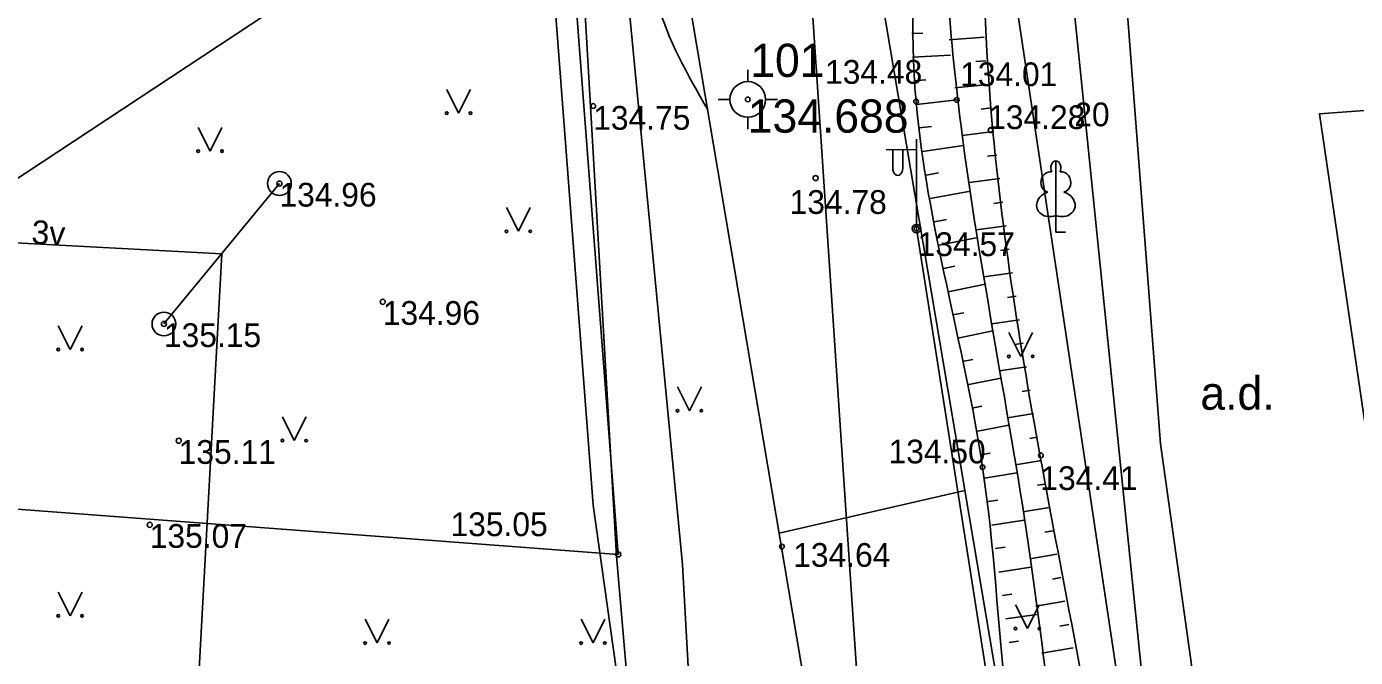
# Model space of a CAD drawing. Extents: x 728710 to 728960, y 272811 to 273475.
# Drawn here: x 728760.53 to 728788.49, y 273391.98 to 273405.27 of the extents above; entities that cross this region are included whole.
import ezdxf

# ---------------------------------------------------------------- set-up
doc = ezdxf.new("R2010")
doc.units = 0
for name, color, linetype in [('Level 10', 7, 'Continuous'), ('Level 12', 7, 'Continuous'), ('Level 15', 7, 'Continuous'), ('Level 18', 7, 'Continuous'), ('Level 20', 7, 'Continuous'), ('Level 21', 7, 'Continuous'), ('Level 23', 7, 'Continuous'), ('Level 25', 7, 'Continuous'), ('Level 26', 7, 'Continuous'), ('Level 28', 7, 'Continuous'), ('Level 30', 7, 'Continuous'), ('Level 32', 7, 'Continuous'), ('Level 34', 7, 'Continuous'), ('Level 35', 7, 'Continuous'), ('Level 4', 7, 'Continuous'), ('Level 42', 7, 'Continuous'), ('Level 48', 7, 'Continuous'), ('Level 53', 7, 'Continuous'), ('Level 57', 7, 'Continuous'), ('Level 63', 7, 'Continuous'), ('Level 8', 7, 'Continuous'), ('RAMI_UZMR_####_####_#', 7, 'Continuous'), ('RELJ_NOGA_####_####_#', 7, 'Continuous'), ('ROBZ_ELEM_####_####_#', 7, 'Continuous'), ('ROBZ_UZMR_####_####_#', 7, 'Continuous'), ('TERT_KOKR_####_####_#', 7, 'Continuous'), ('TERT_KONT_####_####_#', 7, 'Continuous')]:
    doc.layers.add(name, color=color, linetype=linetype)

msp = doc.modelspace()

# ---------------------------------------------------------------- linework, layer by layer
at = {"layer": 'Level 10'}
for p, q in [((728775.704, 273404.108), (728775.704, 273404.358)), ((728775.079, 273403.733), (728775.329, 273403.733)), ((728776.079, 273403.733), (728776.329, 273403.733)), ((728775.704, 273403.108), (728775.704, 273403.358))]:
    msp.add_line(p, q, dxfattribs=at)
for radius in [0.375, 0.05]:
    msp.add_circle((728775.704, 273403.733), radius, dxfattribs=at)
at = {"layer": 'Level 12'}
for p, q in [((728779.155, 273405.124), (728779.386, 273405.129)), ((728780.676, 273405.047), (728779.94, 273404.99)), ((728779.172, 273404.624), (728779.974, 273404.666)), ((728780.717, 273404.548), (728780.501, 273404.529)), ((728779.204, 273404.125), (728779.453, 273404.145)), ((728780.765, 273404.051), (728780.064, 273403.976)), ((728779.253, 273403.628), (728780.101, 273403.724)), ((728780.821, 273403.554), (728780.616, 273403.53)), ((728779.314, 273403.132), (728779.572, 273403.165)), ((728780.881, 273403.057), (728780.214, 273402.975)), ((728779.383, 273402.636), (728780.245, 273402.766)), ((728780.943, 273402.561), (728780.747, 273402.536)), ((728779.46, 273402.142), (728779.718, 273402.185)), ((728781.007, 273402.065), (728780.366, 273401.982)), ((728779.544, 273401.649), (728780.394, 273401.799)), ((728781.072, 273401.57), (728780.884, 273401.544)), ((728779.633, 273401.157), (728779.884, 273401.204)), ((728781.14, 273401.074), (728780.521, 273400.989)), ((728779.726, 273400.666), (728780.547, 273400.825)), ((728781.208, 273400.579), (728781.026, 273400.553)), ((728779.822, 273400.176), (728780.063, 273400.224)), ((728781.279, 273400.084), (728780.679, 273399.998)), ((728779.922, 273399.685), (728780.703, 273399.845)), ((728781.351, 273399.589), (728781.173, 273399.563)), ((728780.022, 273399.196), (728780.25, 273399.243)), ((728780.123, 273398.706), (728780.864, 273398.858)), ((728781.423, 273399.094), (728780.84, 273399.008)), ((728781.498, 273398.6), (728781.325, 273398.574)), ((728780.223, 273398.216), (728780.44, 273398.26)), ((728781.573, 273398.106), (728781.004, 273398.018)), ((728780.322, 273397.726), (728781.03, 273397.867)), ((728781.649, 273397.612), (728781.481, 273397.585)), ((728780.419, 273397.235), (728780.627, 273397.276)), ((728780.512, 273396.744), (728781.198, 273396.872)), ((728781.727, 273397.118), (728781.171, 273397.03)), ((728781.805, 273396.624), (728781.64, 273396.597)), ((728780.6, 273396.252), (728780.805, 273396.288)), ((728781.884, 273396.13), (728781.337, 273396.042)), ((728780.683, 273395.759), (728781.366, 273395.872)), ((728781.964, 273395.636), (728781.8, 273395.61)), ((728780.763, 273395.265), (728780.968, 273395.299)), ((728782.045, 273395.143), (728781.495, 273395.053)), ((728780.841, 273394.772), (728781.521, 273394.878)), ((728782.127, 273394.65), (728781.959, 273394.622)), ((728780.917, 273394.277), (728781.12, 273394.308)), ((728782.21, 273394.157), (728781.637, 273394.06)), ((728780.991, 273393.783), (728781.661, 273393.883)), ((728782.293, 273393.664), (728782.116, 273393.634)), ((728781.065, 273393.288), (728781.263, 273393.317)), ((728782.378, 273393.171), (728781.768, 273393.065)), ((728781.137, 273392.794), (728781.791, 273392.888)), ((728782.464, 273392.678), (728782.274, 273392.646)), ((728781.208, 273392.299), (728781.402, 273392.327)), ((728782.549, 273392.186), (728781.896, 273392.073))]:
    msp.add_line(p, q, dxfattribs=at)
msp.add_spline([(728781.578, 273417.978), (728780.943, 273413.169), (728780.822, 273403.542), (728781.949, 273395.724), (728783.589, 273385.96), (728783.878, 273383.473), (728783.979, 273382.874), (728783.979, 273382.553), (728783.717, 273382.35), (728783.447, 273382.528), (728783.355, 273382.891), (728782.193, 273386.189), (728780.645, 273395.989), (728779.246, 273403.69), (728779.989, 273412.965), (728780.695, 273417.894)], degree=3, dxfattribs=at)
at = {"layer": 'Level 15'}
for centre in [(728765.847, 273401.963), (728763.417, 273399.005)]:
    msp.add_circle(centre, 0.25, dxfattribs=at)
at = {"layer": 'Level 18'}
msp.add_lwpolyline([(728779.523, 273368.911), (728776.197, 273418.56)], dxfattribs=at)
at = {"layer": 'Level 20'}
msp.add_line((728763.417, 273399.005), (728765.848, 273401.962), dxfattribs=at)
at = {"layer": 'Level 21'}
for p, q in [((728764.632, 273400.484), (728747.755, 273401.368)), ((728763.288, 273375.684), (728764.632, 273400.484))]:
    msp.add_line(p, q, dxfattribs=at)
at = {"layer": 'Level 23'}
msp.add_lwpolyline([(728775.104, 273411.821), (728750.664, 273395.692)], dxfattribs=at)
at = {"layer": 'Level 25'}
msp.add_lwpolyline([(728786.021, 273373.071), (728785.768, 273373.044), (728785.616, 273373.092), (728785.488, 273373.338), (728782.365, 273382.337), (728780.872, 273390.743), (728779.255, 273401.013)], dxfattribs=at)
at = {"layer": 'Level 26'}
for p, q in [((728779.255, 273401.013), (728779.255, 273402.896)), ((728779.255, 273402.68), (728778.62, 273402.675)), ((728778.755, 273402.676), (728778.755, 273402.284)), ((728778.965, 273402.678), (728778.965, 273402.284))]:
    msp.add_line(p, q, dxfattribs=at)
msp.add_circle((728779.255, 273401.013), 0.09, dxfattribs=at)
msp.add_ellipse((728778.86, 273402.284), major_axis=(0, 0.151), ratio=0.695971, start_param=1.570796, end_param=4.712389, dxfattribs=at)
at = {"layer": 'Level 28'}
msp.add_lwpolyline([(728781.258, 273406.444), (728784.764, 273383.035), (728785.687, 273382.659)], dxfattribs=at)
at = {"layer": 'Level 30'}
msp.add_spline([(728780.467, 273412.725), (728778.825, 273413.003), (728776.905, 273413.509), (728774.681, 273413.282), (728773.747, 273411.312), (728773.47, 273409.648), (728773.521, 273407.852), (728773.798, 273405.783), (728774.861, 273403.52)], degree=3, dxfattribs=at)
at = {"layer": 'Level 32'}
msp.add_line((728776.368, 273394.599), (728780.273, 273395.496), dxfattribs=at)
at = {"layer": 'Level 34'}
msp.add_spline([(728781.172, 273417.937), (728780.8, 273415.225), (728779.913, 273408.639), (728779.913, 273406.196), (728780.192, 273403.172), (728781.656, 273394.054), (728782.888, 273385.843), (728783.581, 273383.144)], degree=3, dxfattribs=at)
at = {"layer": 'Level 35'}
msp.add_lwpolyline([(728757.526, 273395.316), (728772.98, 273394.153)], dxfattribs=at)
at = {"layer": 'Level 4'}
for p, q in [((728781.219, 273389.895), (728777.803, 273410.117)), ((728777.326, 273388.924), (728773.859, 273409.451))]:
    msp.add_line(p, q, dxfattribs=at)
at = {"layer": 'Level 42'}
msp.add_lwpolyline([(728744.127, 273417.336), (728753.529, 273417.32), (728763.941, 273415.674), (728771.995, 273414.301), (728772.789, 273413.658), (728772.866, 273409.228), (728774.333, 273393.944), (728774.498, 273390.902), (728774.316, 273388.778), (728772.706, 273388.348), (728772.062, 273387.726), (728772.188, 273385.974), (728773.233, 273385.001), (728774.349, 273385.73), (728774.847, 273385.541), (728775.23, 273379.296), (728776.795, 273371.75), (728778.361, 273363.303)], dxfattribs=at)
at = {"layer": 'Level 48'}
for centre, radius in [((728772.451, 273403.594), 0.05), ((728775.704, 273403.733), 0.05), ((728779.246, 273403.69), 0.05), ((728780.101, 273403.724), 0.05), ((728780.814, 273403.086), 0.05), ((728765.848, 273401.962), 0.0534), ((728777.133, 273402.077), 0.0534), ((728779.255, 273401.013), 0.05), ((728768.023, 273399.472), 0.0534), ((728763.417, 273399.006), 0.0534), ((728763.728, 273396.546), 0.0534), ((728780.645, 273395.989), 0.05), ((728781.874, 273396.239), 0.05), ((728763.119, 273394.777), 0.0534), ((728776.423, 273394.317), 0.05), ((728772.98, 273394.153), 0.0534)]:
    msp.add_circle(centre, radius, dxfattribs=at)
at = {"layer": 'Level 8'}
msp.add_line((728772.98, 273394.153), (728771.877, 273408.545), dxfattribs=at)
at = {"layer": 'RAMI_UZMR_####_####_#'}
msp.add_lwpolyline([(728810.773, 273260.978), (728802.611, 273315.901), (728795.796, 273348.362), (728794.274, 273357.438), (728805.771, 273362.009), (728805.234, 273373.998), (728803.936, 273379.727), (728791.234, 273379.578), (728787.734, 273403.429), (728803.558, 273404.599), (728803.908, 273418.239), (728787.419, 273421.679), (728754.475, 273424.404), (728743.982, 273420.563), (728745.23, 273392.888), (728745.879, 273378.489), (728747.149, 273361.103), (728773.116, 273356.557), (728775.22, 273317.659), (728767.872, 273315.668), (728768.286, 273308.258), (728775.846, 273306.093), (728776.746, 273299.712), (728774.767, 273288.109)], dxfattribs=at)
at = {"layer": 'ROBZ_ELEM_####_####_#'}
for points in [[(728775.108, 273376.265), (728772.453, 273395.191), (728770.82, 273416.523)], [(728787.679, 273373.026), (728784.39, 273396.483), (728782.92, 273415.669)]]:
    msp.add_lwpolyline(points, dxfattribs=at)
at = {"layer": 'ROBZ_UZMR_####_####_#'}
for p, q in [((728772.942, 273394.12), (728771.692, 273415.636)), ((728784.885, 273382.939), (728782.32, 273408.103)), ((728774.702, 273373.447), (728772.942, 273394.12))]:
    msp.add_line(p, q, dxfattribs=at)
at = {"layer": 'TERT_KONT_####_####_#'}
for p, q in [((728769.368, 273403.944), (728769.618, 273403.444)), ((728769.618, 273403.444), (728769.868, 273403.944)), ((728764.138, 273403.143), (728764.388, 273402.643)), ((728764.388, 273402.643), (728764.638, 273403.143)), ((728770.626, 273401.456), (728770.876, 273400.956)), ((728770.876, 273400.956), (728771.126, 273401.456)), ((728782.189, 273401.287), (728782.189, 273400.94)), ((728782.189, 273400.94), (728782.389, 273400.94)), ((728761.194, 273398.967), (728761.444, 273398.467)), ((728761.444, 273398.467), (728761.694, 273398.967)), ((728781.2, 273398.824), (728781.45, 273398.324)), ((728781.45, 273398.324), (728781.7, 273398.824)), ((728774.227, 273397.68), (728774.477, 273397.18)), ((728774.477, 273397.18), (728774.727, 273397.68)), ((728765.91, 273397.051), (728766.16, 273396.551)), ((728766.16, 273396.551), (728766.41, 273397.051)), ((728761.194, 273393.361), (728761.444, 273392.861)), ((728761.444, 273392.861), (728761.694, 273393.361)), ((728781.339, 273393.091), (728781.589, 273392.591)), ((728781.589, 273392.591), (728781.839, 273393.091)), ((728767.653, 273392.789), (728767.903, 273392.289)), ((728767.903, 273392.289), (728768.153, 273392.789)), ((728772.198, 273392.789), (728772.448, 273392.289)), ((728772.448, 273392.289), (728772.698, 273392.789))]:
    msp.add_line(p, q, dxfattribs=at)
for points in [[(728782.189, 273402.44), (728782.189, 273401.287)], [(728782.278, 273402.208), (728782.277, 273402.209)]]:
    msp.add_lwpolyline(points, dxfattribs=at)
for centre, radius in [((728769.368, 273403.444), 0.028), ((728769.868, 273403.444), 0.0263), ((728764.138, 273402.643), 0.028), ((728764.638, 273402.643), 0.0263), ((728770.626, 273400.955), 0.028), ((728771.126, 273400.955), 0.0263), ((728761.194, 273398.467), 0.028), ((728761.694, 273398.467), 0.0263), ((728781.2, 273398.323), 0.028), ((728781.7, 273398.323), 0.0263), ((728774.227, 273397.18), 0.028), ((728774.727, 273397.18), 0.0263), ((728765.91, 273396.55), 0.028), ((728766.41, 273396.55), 0.0263), ((728761.194, 273392.86), 0.028), ((728761.694, 273392.86), 0.0263), ((728781.339, 273392.591), 0.028), ((728781.839, 273392.591), 0.0263), ((728767.653, 273392.288), 0.028), ((728768.153, 273392.288), 0.0263), ((728772.197, 273392.288), 0.028), ((728772.697, 273392.288), 0.0263)]:
    msp.add_circle(centre, radius, dxfattribs=at)
for centre, major_axis, ratio, start_param, end_param in [((728782.06, 273401.995), (-0.039, -0.212), 0.861323, 3.141593, 6.283185), ((728782.189, 273402.29), (0, -0.15), 0.707107, 3.14537, 5.287485), ((728782.188, 273402.29), (0, -0.15), 0.707107, 0.995701, 3.137816), ((728782.317, 273401.995), (0.039, -0.212), 0.861323, 0, 3.141593), ((728782.099, 273401.533), (0.307, 0.095), 0.814445, 1.570796, 4.752015), ((728782.278, 273401.533), (-0.307, 0.095), 0.814445, 1.531171, 4.712389)]:
    msp.add_ellipse(centre, major_axis=major_axis, ratio=ratio, start_param=start_param, end_param=end_param, dxfattribs=at)

# ---------------------------------------------------------------- texts
at = {"layer": 'Level 53'}
msp.add_text('3v', height=0.5, rotation=357.0001, dxfattribs=at).set_placement((728760.622, 273400.694))
at = {"layer": 'Level 57'}
for s, p in [('134.48', (728777.331, 273404.063)), ('134.01', (728780.174, 273404.013)), ('134.75', (728772.451, 273403.094)), ('134.28', (728780.764, 273403.109)), ('134.96', (728765.848, 273401.477)), (' 134.78', (728776.399, 273401.323)), ('134.57', (728779.28, 273400.435)), ('134.96', (728768.023, 273398.987)), ('135.15', (728763.417, 273398.52)), ('135.11', (728763.728, 273396.06)), ('134.50', (728778.667, 273396.07)), ('134.41', (728781.862, 273395.509)), (' 135.05', (728769.263, 273394.538)), ('135.07', (728763.119, 273394.292)), ('134.64', (728776.661, 273393.892))]:
    msp.add_text(s, height=0.5, dxfattribs=at).set_placement(p)
at = {"layer": 'Level 63'}
for s, p in [('101', (728775.757, 273404.206)), ('134.688', (728775.704, 273403.033))]:
    msp.add_text(s, height=0.7, dxfattribs=at).set_placement(p)
at = {"layer": 'RELJ_NOGA_####_####_#'}
msp.add_text('20', height=0.5, dxfattribs=at).set_placement((728782.576, 273403.168))
at = {"layer": 'TERT_KOKR_####_####_#'}
msp.add_text('a.d.', height=0.7, dxfattribs=at).set_placement((728785.23, 273397.2))

doc.saveas('drawing.dxf')
